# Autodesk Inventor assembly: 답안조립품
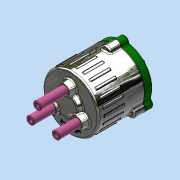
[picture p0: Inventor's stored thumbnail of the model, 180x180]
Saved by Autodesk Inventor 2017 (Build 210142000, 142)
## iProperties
Part Number: 답안조립품
Material: 일반
Document SubType Name: Assembly
Designer: MRC
Author: MRC
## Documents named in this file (15)
- C:\Users\MRC\Desktop\620811V1002\답안조립품.iam
- C:\Users\MRC\Desktop\620811V1002\본체.ipt
- C:\Users\MRC\Desktop\620811V1002\가변스프링1.ipt
- C:\Users\MRC\Desktop\620811V1002\가변스프링2.ipt
- C:\Users\MRC\Desktop\620811V1002\가변스프링3.ipt
- C:\Users\MRC\Desktop\620811V1002\개스킷.ipt
- C:\Users\MRC\Desktop\620811V1002\멈춤링 10x1.ipt
- C:\Users\MRC\Desktop\620811V1002\멈춤링 22x1.2.ipt
- C:\Users\MRC\Desktop\620811V1002\메인 축.ipt
- C:\Users\MRC\Desktop\620811V1002\베어링 NA 4900.ipt
- C:\Users\MRC\Desktop\620811V1002\볼트 M5.ipt
- C:\Users\MRC\Desktop\620811V1002\슬라이드 축.ipt
- C:\Users\MRC\Desktop\620811V1002\오일 실.ipt
- C:\Users\MRC\Desktop\620811V1002\커버.ipt
- C:\Users\MRC\Desktop\620811V1002\판캠.ipt
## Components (4 placed, 4 different names)
1. 개스킷:1
2. 가변스프링1:1
3. 가변스프링2:1
4. 가변스프링3:1
